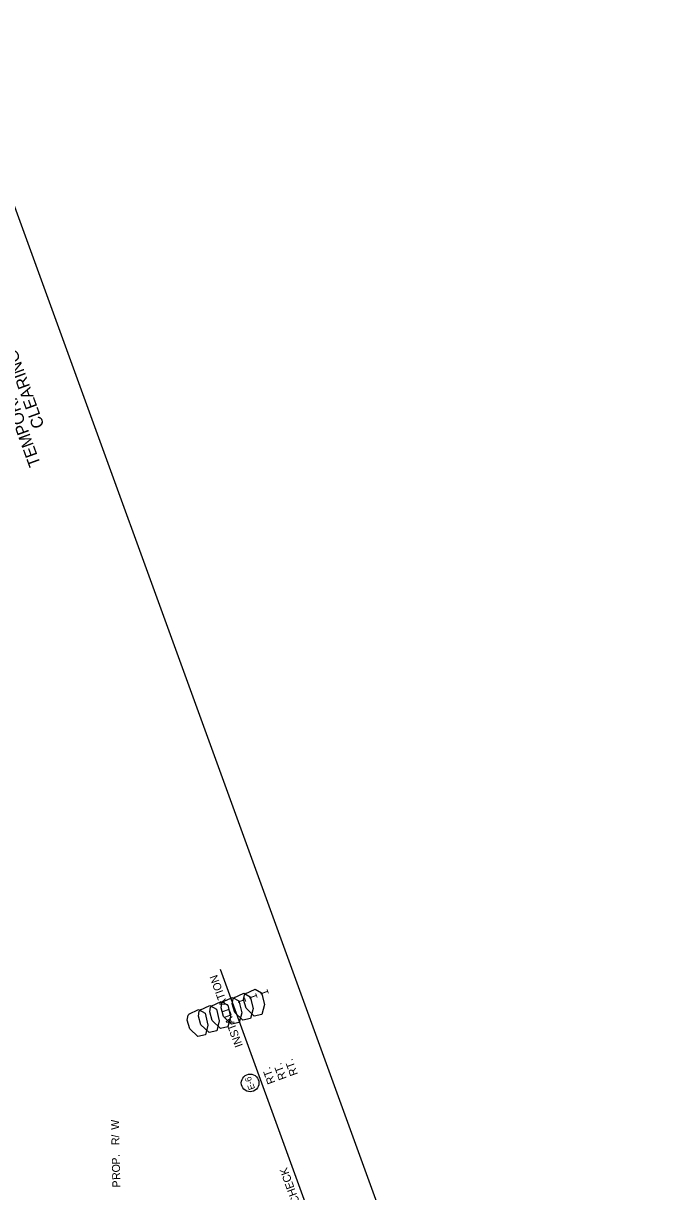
# Model space of a CAD drawing. Extents: x 986289 to 987754, y 1871116 to 1873096.
# Drawn here: x 987265 to 987754, y 1872096 to 1872971 of the extents above; entities that cross this region are included whole.
import ezdxf

# ---------------------------------------------------------------- set-up
doc = ezdxf.new("R2010")
doc.units = 0
for name, color, linetype in [('1', 7, 'Continuous'), ('44', 7, 'Continuous'), ('60', 7, 'Continuous'), ('NO PLOT', 7, 'Continuous'), ('R_Draft', 7, 'Continuous'), ('S_TREE', 7, 'Continuous')]:
    doc.layers.add(name, color=color, linetype=linetype)

msp = doc.modelspace()

# ---------------------------------------------------------------- linework, layer by layer
at = {"layer": '1'}
msp.add_circle((987434.66, 1872177.04), 6.61, dxfattribs=at)
at = {"layer": '44'}
msp.add_line((987494.89, 1872035.61), (987412.46, 1872262.08), dxfattribs=at)
at = {"layer": 'NO PLOT'}
msp.add_lwpolyline([(987753.66, 1871472.09), (987208.01, 1872971.24), (986718.28, 1872792.99), (986821.23, 1872510.15), (986884.66, 1872533.24), (987030.02, 1872133.87), (986966.59, 1872110.78), (987064.47, 1871841.86), (987122.5, 1871862.99), (987239.7, 1871540.99), (987181.66, 1871519.87), (987263.93, 1871293.85)], close=True, dxfattribs=at)
msp.add_lwpolyline([(987753.66, 1871472.09), (987208.01, 1872971.24), (986718.28, 1872792.99), (986821.23, 1872510.15), (986884.66, 1872533.24), (987030.02, 1872133.87), (986966.59, 1872110.78), (987064.47, 1871841.86), (987122.5, 1871862.99), (987239.7, 1871540.99), (987181.66, 1871519.87), (987263.93, 1871293.85)], close=True, dxfattribs=at)
msp.add_lwpolyline([(987753.66, 1871472.09), (987208.01, 1872971.24), (986718.28, 1872792.99), (986821.23, 1872510.15), (986884.66, 1872533.24), (987030.02, 1872133.87), (986966.59, 1872110.78), (987064.47, 1871841.86), (987122.5, 1871862.99), (987239.7, 1871540.99), (987181.66, 1871519.87), (987263.93, 1871293.85)], close=True, dxfattribs=at)
at = {"layer": 'S_TREE'}
for points in [[(987422.42, 1872240.81), (987429.89, 1872244.3), (987434.72, 1872241.56), (987436.87, 1872232.74), (987434.94, 1872225.35), (987429.23, 1872224.08), (987423.15, 1872229.97), (987421.3, 1872236.41), (987421.91, 1872240.07), (987423.1, 1872241.29)], [(987422.42, 1872240.81), (987429.89, 1872244.3), (987434.72, 1872241.56), (987436.87, 1872232.74), (987434.94, 1872225.35), (987429.23, 1872224.08), (987423.15, 1872229.97), (987421.3, 1872236.41), (987421.91, 1872240.07), (987423.1, 1872241.29)], [(987430.88, 1872243.89), (987438.35, 1872247.38), (987443.18, 1872244.64), (987445.33, 1872235.81), (987443.39, 1872228.43), (987437.69, 1872227.16), (987431.61, 1872233.04), (987429.75, 1872239.49), (987430.37, 1872243.14), (987431.56, 1872244.37)], [(987430.88, 1872243.89), (987438.35, 1872247.38), (987443.18, 1872244.64), (987445.33, 1872235.81), (987443.39, 1872228.43), (987437.69, 1872227.16), (987431.61, 1872233.04), (987429.75, 1872239.49), (987430.37, 1872243.14), (987431.56, 1872244.37)], [(987397.05, 1872231.58), (987404.52, 1872235.06), (987409.35, 1872232.33), (987411.5, 1872223.5), (987409.57, 1872216.12), (987403.86, 1872214.85), (987397.78, 1872220.73), (987395.93, 1872227.18), (987396.54, 1872230.83), (987397.73, 1872232.05)], [(987397.05, 1872231.58), (987404.52, 1872235.06), (987409.35, 1872232.33), (987411.5, 1872223.5), (987409.57, 1872216.12), (987403.86, 1872214.85), (987397.78, 1872220.73), (987395.93, 1872227.18), (987396.54, 1872230.83), (987397.73, 1872232.05)], [(987405.51, 1872234.66), (987412.98, 1872238.14), (987417.81, 1872235.41), (987419.96, 1872226.58), (987418.02, 1872219.2), (987412.32, 1872217.93), (987406.24, 1872223.81), (987404.38, 1872230.26), (987404.99, 1872233.91), (987406.19, 1872235.13)], [(987405.51, 1872234.66), (987412.98, 1872238.14), (987417.81, 1872235.41), (987419.96, 1872226.58), (987418.02, 1872219.2), (987412.32, 1872217.93), (987406.24, 1872223.81), (987404.38, 1872230.26), (987404.99, 1872233.91), (987406.19, 1872235.13)], [(987413.96, 1872237.73), (987421.44, 1872241.22), (987426.27, 1872238.49), (987428.42, 1872229.66), (987426.48, 1872222.28), (987420.78, 1872221), (987414.7, 1872226.89), (987412.84, 1872233.33), (987413.45, 1872236.99), (987414.65, 1872238.21)], [(987413.96, 1872237.73), (987421.44, 1872241.22), (987426.27, 1872238.49), (987428.42, 1872229.66), (987426.48, 1872222.28), (987420.78, 1872221), (987414.7, 1872226.89), (987412.84, 1872233.33), (987413.45, 1872236.99), (987414.65, 1872238.21)], [(987388.59, 1872228.5), (987396.06, 1872231.99), (987400.89, 1872229.25), (987403.04, 1872220.42), (987401.11, 1872213.04), (987395.4, 1872211.77), (987389.33, 1872217.65), (987387.47, 1872224.1), (987388.08, 1872227.75), (987389.27, 1872228.97)]]:
    msp.add_lwpolyline(points, dxfattribs=at)

# ---------------------------------------------------------------- texts
at = {"layer": '1'}
msp.add_text('E-6 ', height=4.8, rotation=110, dxfattribs=at).set_placement((987438.4, 1872172.87))
at = {"layer": '44'}
for s, p in [('INSTALLATION', (987429.24, 1872205.02)), ('1', (987440.45, 1872240.55)), ('1', (987448.91, 1872243.63)), ('1', (987431.99, 1872237.47)), ('RT.', (987462.13, 1872180.51)), ('RT.', (987470.58, 1872183.59)), ('RT.', (987453.67, 1872177.43)), ('ROCK DITCH CHECK', (987489.72, 1872038.83))]:
    msp.add_text(s, height=6, rotation=110, dxfattribs=at).set_placement(p)
at = {"layer": '60'}
for s, p in [('TEMPORARY EROSION CONTROL DETAILS', (987277.82, 1872640.76)), ('CLEARING AND GRUBBING STAGE', (987280.51, 1872669.57))]:
    msp.add_text(s, height=9, rotation=110, dxfattribs=at).set_placement(p)
at = {"layer": 'R_Draft'}
for s, p in [('W', (987336.47, 1872142.02)), ('/', (987336.6, 1872136.16)), ('R', (987336.72, 1872130.5)), ('P', (987337.03, 1872115.9)), ('.', (987336.91, 1872121.57)), ('O', (987337.15, 1872110.04)), ('R', (987337.27, 1872104.38)), ('P', (987337.39, 1872098.71))]:
    msp.add_text(s, height=6, rotation=91.20729, dxfattribs=at).set_placement(p)

doc.saveas('drawing.dxf')
